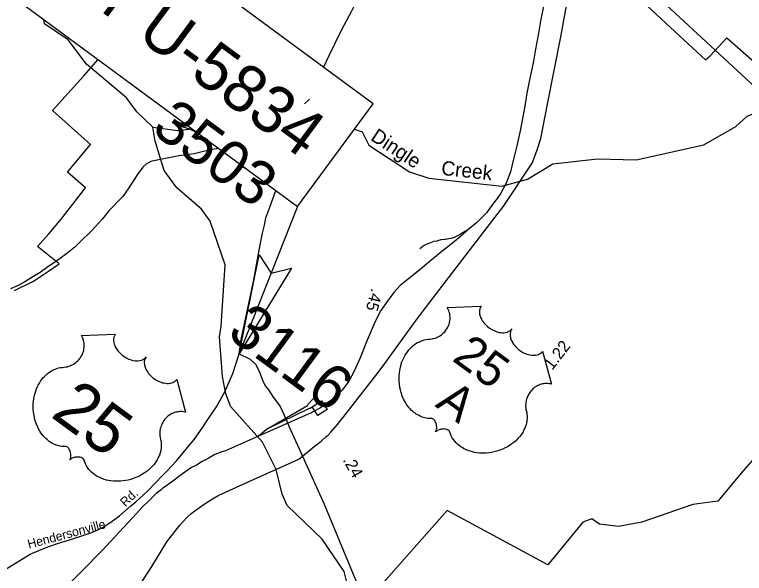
# Model space of a CAD drawing. Extents: x 945666 to 965748, y 644452 to 663300.
# Drawn here: x 953745 to 954740, y 659246 to 660009 of the extents above; entities that cross this region are included whole.
import ezdxf

# ---------------------------------------------------------------- set-up
doc = ezdxf.new("R2010")
doc.units = 0
for name, color, linetype in [('Default', 7, 'Continuous'), ('Exist Boundary Political City Limit New', 7, 'Continuous'), ('Exist Hydrographic Creek Single Shore', 7, 'Continuous'), ('Exist Hydrographic Misc Water Feature', 7, 'Continuous'), ('Exist Railroad Mainline', 7, 'Continuous'), ('Exist Railroad Station CELL', 7, 'Continuous'), ('Exist Road Primary US Label', 7, 'Continuous'), ('Exist Road Primary US Mileage Hundredths English Label', 7, 'Continuous'), ('Exist Road Primary US Shield Number Label', 7, 'Continuous'), ('Exist Road Primary US UnDivided 4 Lane Attributed', 7, 'Continuous'), ('Exist Road Secondary Mileage Tenths English Label', 7, 'Continuous'), ('Exist Road Secondary Type 51 Attributed', 7, 'Continuous'), ('Old_Level_1', 7, 'Continuous'), ('Old_Level_28', 7, 'Continuous'), ('Old_Level_48', 7, 'Continuous'), ('Prop EOT', 7, 'Continuous'), ('Prop Paved Shoulder', 7, 'Continuous'), ('Prop Terminator CELL', 7, 'Continuous')]:
    doc.layers.add(name, color=color, linetype=linetype)

msp = doc.modelspace()

# ---------------------------------------------------------------- linework, layer by layer
at = {"layer": 'Default'}
for points in [[(954051.13, 659546.04), (954065.89, 659538.88), (954073.22, 659532.08), (954078.17, 659522.36), (954082.73, 659509.91), (954086.54, 659502.22), (954090.86, 659496.7), (954097.47, 659486.7), (954102.05, 659481.22), (954107.02, 659474.06), (954115.33, 659456.27)], [(954115.33, 659456.27), (954119.23, 659446.4), (954137.42, 659406.62)], [(954137.42, 659406.62), (954167.04, 659340.74), (954214.25, 659226.89), (954219.17, 659214.5), (954234.76, 659177.83), (954248.16, 659148.39), (954278.06, 659087), (954292.16, 659061.01), (954331.21, 658991.49), (954355.24, 658946.97), (954361.3, 658935.37), (954368.18, 658920.76), (954371.98, 658911.32)]]:
    msp.add_lwpolyline(points, dxfattribs=at)
at = {"layer": 'Exist Boundary Political City Limit New'}
for points in [[(954575.32, 660503.3), (954575.7, 660500.3), (954583.86, 660480.88), (954594.94, 660465.46), (954605.03, 660449.51), (954618.55, 660420.1), (954630.56, 660394.58), (954633.25, 660364.3), (954630.95, 660333.19), (954616.56, 660298.85), (954554.44, 660217.43), (954494.31, 660125.89), (954651.37, 659980)], [(954651.37, 659980), (954686.77, 659947.19), (954692.96, 659952.82), (954715.96, 659977.25), (954922.31, 659795.6)], [(953744.79, 659632.28), (953770.6, 659644.99), (953791.02, 659658.63), (953805.5, 659668.87), (953776.31, 659692.7), (953791.81, 659709.74), (953808.51, 659729.83), (953841.4, 659772.67), (953817.2, 659793.89), (953848.59, 659831.85), (953796.78, 659878.21), (953839.23, 659925.52), (953858.88, 659947.47)], [(954764.84, 659416.94), (954738.12, 659386.29), (954703.48, 659345.2), (954669.25, 659340.27), (954599.91, 659316.21), (954568.17, 659310.66), (954542.24, 659313.52), (954531.6, 659320.72), (954519.65, 659316.53), (954471.84, 659258.02), (954334.37, 659332.51), (954199.61, 659179.31), (954181.17, 659196.36), (954156.43, 659171.36), (954118.74, 659203), (954109.85, 659196.66), (954100.54, 659204.87), (954083.83, 659205.72), (953921.01, 659022.58), (953828.63, 659098.16), (953806.55, 659063.26), (953767.75, 659001.98), (953738.57, 658955.88)]]:
    msp.add_lwpolyline(points, dxfattribs=at)
at = {"layer": 'Exist Hydrographic Creek Single Shore'}
for points in [[(953933.56, 659855.16), (953911.36, 659876), (953897.59, 659895.18), (953842.79, 659941.09), (953818.19, 659974.51), (953785.69, 659996.28), (953784.71, 660002.17)], [(954208.11, 659852.7), (954218.79, 659848.76), (954227.82, 659830.52), (954283.37, 659794.26), (954309.81, 659785.77), (954409.1, 659775.01), (954444.04, 659784.17), (954478.8, 659805.3), (954539.64, 659812.28), (954592.2, 659810.59), (954684.49, 659831.02), (954727.97, 659856.19), (954743.28, 659870.22), (954779.41, 659884.38), (954824.39, 659921.85), (954835.26, 659928.55), (954851.86, 659930.3), (954933.17, 659961.32), (954972.81, 659985.14)], [(954026.31, 659583.85), (954032.05, 659667.6), (954011.45, 659726.99), (953999.72, 659743.54), (953966.11, 659772.61), (953948.83, 659796.12), (953936.49, 659836.25), (953933.56, 659855.16)], [(953933.56, 659855.16), (953967.32, 659850.7), (953987.02, 659852.97)], [(954285.98, 659018.04), (954256.55, 659113.26), (954202.7, 659214.34), (954194.18, 659248.85), (954164.42, 659293.23), (954116.6, 659339.14), (954109.6, 659354.74), (954101.67, 659388.26), (954082.77, 659425.37), (954039.54, 659473.66), (954033.02, 659491.57), (954028.3, 659515.14), (954024.39, 659569.26), (954026.31, 659583.85)]]:
    msp.add_lwpolyline(points, dxfattribs=at)
at = {"layer": 'Exist Hydrographic Misc Water Feature'}
for p, q in [((954140.27, 659887.27), (954146.78, 659893.38)), ((954056.52, 659759.69), (954058.09, 659762.09))]:
    msp.add_line(p, q, dxfattribs=at)
for points in [[(953963.91, 659859.08), (953983.16, 659852.81), (953994.99, 659847.09)], [(954050.29, 659806.3), (954054.47, 659801.8), (954060.15, 659798.94), (954060.27, 659798.94)]]:
    msp.add_lwpolyline(points, dxfattribs=at)
at = {"layer": 'Exist Railroad Mainline'}
msp.add_line((954090.14, 659444.22), (954077.64, 659433.83), dxfattribs=at)
for points in [[(954467.99, 660031.57), (954462.18, 660002.69), (954459.26, 659983.44), (954454.84, 659961.67), (954452.12, 659945.27), (954446.3, 659917.49), (954443.27, 659901.53), (954440.44, 659884.14), (954437.5, 659869.62), (954433.96, 659850.19), (954429.73, 659829.79), (954424.48, 659809.75), (954420.71, 659794.15), (954414.8, 659778.91), (954407.54, 659765.13), (954402.68, 659758.12), (954397.35, 659751.04), (954388.13, 659738.55), (954374.42, 659724.58), (954362.54, 659715.21)], [(954362.54, 659715.21), (954354.82, 659707.82), (954341.9, 659697.11), (954325.24, 659683.68), (954312.12, 659673.34), (954294.93, 659658.81), (954281.92, 659648.39), (954270.62, 659639.22), (954261.91, 659629.79), (954252.6, 659617.6), (954243.99, 659605.29), (954236.24, 659589.96), (954225.6, 659564.59), (954216.17, 659540.44), (954207.53, 659521.71), (954200.59, 659508.77), (954191.57, 659496.56), (954177.37, 659483.39), (954168.9, 659477.21), (954165.58, 659474.98), (954161.86, 659472.52), (954153.1, 659467.85), (954148.71, 659465.21), (954148.19, 659464.96), (954077.64, 659433.83)], [(954362.54, 659715.21), (954359.79, 659713.24), (954352.14, 659708.81), (954347.85, 659706.73), (954343.97, 659704.76), (954339.49, 659703.26), (954336.72, 659702.81), (954332.24, 659702.17), (954331.12, 659701.96), (954326.71, 659701.47), (954325.99, 659701.38), (954321.21, 659700.33), (954320.28, 659699.96), (954316.28, 659699.17), (954309.37, 659696.74), (954305.9, 659695.11), (954303.33, 659693.65), (954297.14, 659689.16)], [(954090.14, 659444.22), (954144.03, 659475.69), (954145.34, 659477.26), (954150.22, 659482.98), (954155.17, 659487.63)], [(954090.14, 659444.22), (954146.95, 659471.73), (954147.84, 659472.12), (954151.72, 659474.51), (954155.09, 659476.65), (954158.01, 659479.13), (954160.06, 659481.51)], [(954077.64, 659433.83), (954032.56, 659413.87), (954027.66, 659412.26), (954018.07, 659408.66), (954008.94, 659403.21), (954000.46, 659398.98), (953992.93, 659394.01), (953986.11, 659390.87), (953973.97, 659382.36), (953958.83, 659370.77), (953946.62, 659362.1), (953944.59, 659360.43), (953938.6, 659355.79), (953928.94, 659346.44), (953918.18, 659336.22), (953911.09, 659328.12), (953905.21, 659321.67), (953870.08, 659284.17), (953864.21, 659277.93), (953855.1, 659268.59), (953846.88, 659259.86), (953836.11, 659249.21), (953832.76, 659245.77), (953650.24, 659062.44)]]:
    msp.add_lwpolyline(points, dxfattribs=at)
at = {"layer": 'Exist Railroad Station CELL'}
msp.add_lwpolyline([(954150.7, 659473.81), (954163.51, 659481.89), (954170.88, 659470.19), (954158.07, 659462.11)], close=True, dxfattribs=at)
at = {"layer": 'Exist Road Primary US UnDivided 4 Lane Attributed'}
for points in [[(954166.15, 659936.93), (954173.67, 659953.1), (954191.19, 659988.51), (954203.96, 660013.16), (954216.08, 660037.19), (954238.63, 660083.24), (954250.32, 660104.79), (954275.33, 660155.8), (954297.13, 660200.77), (954318.86, 660245.17), (954341.95, 660289.24), (954345.28, 660295.92), (954361.28, 660325.76), (954378.42, 660354.96), (954388.59, 660372.01), (954399.02, 660390.77), (954411.46, 660414.96), (954416.59, 660426.81), (954422.43, 660438.53), (954423.93, 660442.39)], [(954137.42, 659406.62), (954153.43, 659419.44), (954162.73, 659427.06), (954169.5, 659433.08), (954171.92, 659434.71), (954176.2, 659439.21), (954181.86, 659445.78), (954184.91, 659449.54), (954189.71, 659455.46), (954193.54, 659460.58), (954237.18, 659516.36), (954247.47, 659529.67), (954289.94, 659588.86), (954303.7, 659607.2), (954346.83, 659663.43), (954411.69, 659747.87), (954450.6, 659806.4), (954456.95, 659823.05), (954462.05, 659839.94), (954471.18, 659886.69), (954489.3, 659978.73), (954499.89, 660036.2)], [(954051.13, 659546.04), (954053.84, 659565.73), (954070.56, 659644.84), (954079.89, 659694.87), (954082.76, 659710.85), (954085.47, 659721.4), (954087.43, 659731.55), (954092.99, 659746.35), (954101, 659768.91)], [(953729.79, 659250.65), (953766.36, 659272.53), (953786.59, 659281.37), (953802.15, 659286.8), (953827.08, 659294.71), (953838.01, 659298.11), (953848.68, 659301.88), (953857.55, 659305.39), (953864.58, 659308.97), (953874.62, 659315.54), (953887.97, 659325.14), (953903.29, 659338.5), (953909.58, 659343.65), (953916.27, 659349.78), (953926.19, 659358.61), (953947.15, 659380.31), (953953, 659386.55), (953965.43, 659400.04), (953989.78, 659429.34), (954000.5, 659444.54), (954010.19, 659459.24), (954020.31, 659473.61), (954031.72, 659494.3), (954042.61, 659519.37), (954051.13, 659546.04)], [(953872.78, 659163.87), (953879.82, 659174.92), (953909.71, 659220.77), (953916.18, 659231.14), (953931.95, 659255.99), (953952.66, 659289.4), (953970.09, 659312.1), (953980.01, 659323.09), (953984.98, 659327.65), (953992.31, 659333.42), (954004.62, 659342.01), (954014.69, 659348.25), (954022.49, 659352.55), (954042.24, 659361.63), (954062.46, 659370.95), (954132.38, 659402.25), (954137.42, 659406.62)]]:
    msp.add_lwpolyline(points, dxfattribs=at)
at = {"layer": 'Exist Road Secondary Type 51 Attributed'}
msp.add_lwpolyline([(954023.53, 659826.04), (954013.81, 659825.01), (954011.56, 659824.33), (953989.64, 659819), (953968.77, 659816.16), (953932.69, 659809.07), (953930.85, 659808.29), (953924.37, 659804.73), (953919.95, 659800.68), (953911.87, 659790.07), (953900.51, 659772.55), (953892.31, 659760.78), (953873.36, 659741.25), (953864.65, 659730.3), (953849.92, 659713.94), (953834.03, 659698.2), (953827.22, 659691.63), (953817.87, 659684.26), (953808.7, 659677.64), (953799.26, 659670.88), (953790.32, 659664.81), (953779.88, 659657.17), (953770.02, 659651.06), (953759.14, 659644.29), (953749.71, 659639.48), (953739.41, 659634.94)], dxfattribs=at)
at = {"layer": 'Old_Level_28'}
msp.add_lwpolyline([(954708.22, 660405.29), (954708.61, 660402.28), (954716.76, 660382.87), (954727.84, 660367.45), (954737.94, 660351.5), (954751.45, 660322.09), (954763.46, 660296.56), (954766.15, 660266.28), (954763.85, 660235.17), (954749.46, 660200.83), (954687.34, 660119.41), (954627.21, 660027.87), (954784.27, 659881.98)], dxfattribs=at)
at = {"layer": 'Prop EOT'}
msp.add_line((954130.35, 659747.26), (954051.13, 659546.04), dxfattribs=at)
msp.add_lwpolyline([(954233.56, 659887.22), (953266.51, 660600.43), (953163.29, 660460.48), (954130.35, 659747.26)], close=True, dxfattribs=at)
at = {"layer": 'Prop Terminator CELL'}
for points in [[(954122.21, 659663.14), (954051.13, 659546.04), (954078.52, 659681.14), (954094.54, 659656.3)], [(954380.94, 659611.04), (954380.12, 659609.78), (954379.36, 659608.13), (954379.04, 659607.22), (954378.67, 659605.31), (954378.54, 659602.82), (954378.87, 659600.04), (954379.56, 659597.33), (954380.17, 659595.7), (954381.37, 659593.16), (954382.93, 659590.55), (954384.92, 659587.96), (954387.11, 659585.55), (954389.69, 659583.17), (954392.43, 659581.07), (954395.59, 659579.08), (954399.38, 659577.27), (954401.2, 659576.54), (954403.34, 659575.86), (954405.42, 659575.35), (954407.85, 659575), (954409.9, 659574.86), (954411.59, 659574.85), (954414.23, 659575.19), (954416.6, 659575.82), (954417.75, 659576.3), (954418.81, 659576.79), (954420.72, 659578.1), (954421.47, 659578.75), (954422.78, 659580.28), (954421.88, 659578.85), (954421.4, 659577.9), (954421.01, 659576.9), (954420.71, 659575.77), (954420.41, 659574.07), (954420.34, 659572.52), (954420.51, 659570.03), (954420.76, 659568.67), (954421.05, 659567.52), (954422.03, 659564.69), (954423.49, 659561.81), (954424.26, 659560.47), (954425.12, 659559.19), (954426.28, 659557.65), (954427.54, 659556.15), (954428.87, 659554.77), (954430.26, 659553.4), (954431.76, 659552.11), (954433.02, 659551.12), (954434.62, 659549.97), (954436.15, 659548.98), (954437.78, 659548.04), (954439.64, 659547.1), (954441.19, 659546.41), (954443.29, 659545.58), (954445.3, 659544.98), (954447.14, 659544.55), (954449.65, 659544.16), (954451.79, 659544), (954453.5, 659544.07), (954455.64, 659544.3), (954457.88, 659544.81), (954459.34, 659545.31), (954460.61, 659545.99), (954461.89, 659546.75), (954463.04, 659547.72), (954463.93, 659548.63), (954464.6, 659549.48), (954476.65, 659504.67), (954475.77, 659504.92), (954473.61, 659505.31), (954471.8, 659505.5), (954468.75, 659505.57), (954467.31, 659505.42), (954465.85, 659505.25), (954464.42, 659504.97), (954463.12, 659504.68), (954461.41, 659504.13), (954459.79, 659503.51), (954458.09, 659502.76), (954456.72, 659502.04), (954454.09, 659500.36), (954452.57, 659499.19), (954451.36, 659498.14), (954449.1, 659495.78), (954448.09, 659494.61), (954447.19, 659493.38), (954446.3, 659492.03), (954445.51, 659490.7), (954444.78, 659489.24), (954444.14, 659487.95), (954443.48, 659486.29), (954442.8, 659484.28), (954442.28, 659482.24), (954441.74, 659478.72), (954441.55, 659474.86), (954441.71, 659472.51), (954442, 659470.38), (954442.68, 659467.53), (954443.02, 659465.95), (954443.31, 659464), (954443.57, 659460.53), (954443.58, 659458.98), (954443.5, 659457.3), (954443.34, 659455.64), (954443.11, 659453.89), (954442.86, 659452.39), (954442.04, 659449.13), (954441, 659446.15), (954440.4, 659444.62), (954438.83, 659441.35), (954437.99, 659439.78), (954436.16, 659436.82), (954433.67, 659433.43), (954431.04, 659430.41), (954427.68, 659427.11), (954425.52, 659425.24), (954422.83, 659423.2), (954420.42, 659421.48), (954416.63, 659419.14), (954413.67, 659417.59), (954410.05, 659415.9), (954407.73, 659414.96), (954405.16, 659414.04), (954402.07, 659413.06), (954398.62, 659412.14), (954394.72, 659411.37), (954391.69, 659410.91), (954387.91, 659410.55), (954385.7, 659410.43), (954382.63, 659410.4), (954378.62, 659410.59), (954374.83, 659411.01), (954371.72, 659411.52), (954369.08, 659412.13), (954365.77, 659413.06), (954360.58, 659415.05), (954358.77, 659415.88), (954356.7, 659416.98), (954354.83, 659418.09), (954353.06, 659419.23), (954350.79, 659420.91), (954348.65, 659422.75), (954346.74, 659424.64), (954344.86, 659426.74), (954343.04, 659429.15), (954341.54, 659431.54), (954340.18, 659434.17), (954338.24, 659439.11), (954337.61, 659440.43), (954337.14, 659441.02), (954335.79, 659442.12), (954334.27, 659442.81), (954332.53, 659443.27), (954331.41, 659443.44), (954329.81, 659443.52), (954328.49, 659443.48), (954326.79, 659443.27), (954325.52, 659442.98), (954324.53, 659442.75), (954322.33, 659441.9), (954321.41, 659441.4), (954320.3, 659440.7), (954318.9, 659439.5), (954319.79, 659441.66), (954320.15, 659443.27), (954320.29, 659444.76), (954320.32, 659446.15), (954320.17, 659448.08), (954319.9, 659449.63), (954319.46, 659451.34), (954318.81, 659452.91), (954318.22, 659454.09), (954317.6, 659455.05), (954316.74, 659456.09), (954315.93, 659456.8), (954315.21, 659457.3), (954314.07, 659457.8), (954312.05, 659457.82), (954310.16, 659457.88), (954308.18, 659458.04), (954305.92, 659458.37), (954304.32, 659458.69), (954302.5, 659459.19), (954300.44, 659459.86), (954298.3, 659460.71), (954296.19, 659461.71), (954294.37, 659462.65), (954292.52, 659463.78), (954290.91, 659464.88), (954289.28, 659466.11), (954287.84, 659467.36), (954286.18, 659468.83), (954284.21, 659470.78), (954282.69, 659472.55), (954281.14, 659474.49), (954279.61, 659476.57), (954278.09, 659478.95), (954276.28, 659482.07), (954275.14, 659484.38), (954273.46, 659488.2), (954271.79, 659493.08), (954270.75, 659497.07), (954270.12, 659500.17), (954269.43, 659505.05), (954269.16, 659508.1), (954269.04, 659513.3), (954269.17, 659516.91), (954269.41, 659519.45), (954269.95, 659523.43), (954270.4, 659525.84), (954271.21, 659529.24), (954272.08, 659532.25), (954273.01, 659535.03), (954273.68, 659536.74), (954274.97, 659539.65), (954275.95, 659541.68), (954277.41, 659544.35), (954279.13, 659547.06), (954280.84, 659549.45), (954282.35, 659551.37), (954284.27, 659553.5), (954286.45, 659555.65), (954288.46, 659557.39), (954289.99, 659558.58), (954291.96, 659559.96), (954294.27, 659561.37), (954296.66, 659562.59), (954298.76, 659563.52), (954301.19, 659564.39), (954303.41, 659565.02), (954306.1, 659565.54), (954308.75, 659565.88), (954311.03, 659565.98), (954313.94, 659566.39), (954315.56, 659566.75), (954317.65, 659567.36), (954319.45, 659568.03), (954320.97, 659568.69), (954323.12, 659569.75), (954324.6, 659570.63), (954326.72, 659572.1), (954328.08, 659573.23), (954329.73, 659574.76), (954331.19, 659576.26), (954332.82, 659578.29), (954334.04, 659580.05), (954335.3, 659582.24), (954336.35, 659584.45), (954337.14, 659586.48), (954337.84, 659588.95), (954338.22, 659590.85), (954338.51, 659593.59), (954338.58, 659596.29), (954338.37, 659598.69), (954338.03, 659600.93), (954337.5, 659602.82), (954336.94, 659604.53), (954336.12, 659606.53), (954335.21, 659608.29), (954334.57, 659609.31)], [(953882.27, 659572.75), (953881.45, 659571.48), (953880.69, 659569.83), (953880.36, 659568.93), (953879.99, 659567.02), (953879.86, 659564.53), (953880.2, 659561.75), (953880.88, 659559.03), (953881.5, 659557.41), (953882.7, 659554.87), (953884.26, 659552.25), (953886.24, 659549.67), (953888.43, 659547.26), (953891.01, 659544.87), (953893.75, 659542.77), (953896.92, 659540.78), (953900.7, 659538.98), (953902.53, 659538.24), (953904.67, 659537.57), (953906.74, 659537.06), (953909.17, 659536.7), (953911.23, 659536.57), (953912.91, 659536.56), (953915.56, 659536.9), (953917.92, 659537.52), (953919.08, 659538), (953920.14, 659538.5), (953922.05, 659539.81), (953922.79, 659540.46), (953924.11, 659541.98), (953923.21, 659540.55), (953922.72, 659539.61), (953922.34, 659538.61), (953922.03, 659537.48), (953921.74, 659535.78), (953921.66, 659534.23), (953921.83, 659531.74), (953922.08, 659530.38), (953922.38, 659529.23), (953923.36, 659526.4), (953924.81, 659523.52), (953925.58, 659522.18), (953926.45, 659520.9), (953927.6, 659519.35), (953928.87, 659517.86), (953930.2, 659516.48), (953931.58, 659515.11), (953933.08, 659513.82), (953934.35, 659512.83), (953935.95, 659511.68), (953937.48, 659510.68), (953939.11, 659509.75), (953940.97, 659508.8), (953942.51, 659508.12), (953944.61, 659507.29), (953946.62, 659506.68), (953948.46, 659506.26), (953950.98, 659505.87), (953953.12, 659505.7), (953954.82, 659505.78), (953956.96, 659506.01), (953959.2, 659506.52), (953960.66, 659507.01), (953961.94, 659507.7), (953963.22, 659508.46), (953964.37, 659509.42), (953965.26, 659510.34), (953965.93, 659511.19), (953977.97, 659466.38), (953977.09, 659466.63), (953974.93, 659467.02), (953973.13, 659467.21), (953970.07, 659467.27), (953968.64, 659467.13), (953967.18, 659466.96), (953965.75, 659466.68), (953964.45, 659466.38), (953962.74, 659465.83), (953961.11, 659465.22), (953959.42, 659464.47), (953958.05, 659463.75), (953955.42, 659462.06), (953953.89, 659460.9), (953952.69, 659459.84), (953950.42, 659457.49), (953949.42, 659456.31), (953948.51, 659455.09), (953947.63, 659453.74), (953946.83, 659452.41), (953946.1, 659450.95), (953945.47, 659449.66), (953944.8, 659447.99), (953944.12, 659445.99), (953943.6, 659443.95), (953943.07, 659440.43), (953942.88, 659436.57), (953943.03, 659434.22), (953943.32, 659432.08), (953944, 659429.24), (953944.34, 659427.65), (953944.64, 659425.71), (953944.9, 659422.23), (953944.9, 659420.69), (953944.83, 659419.01), (953944.66, 659417.35), (953944.44, 659415.59), (953944.19, 659414.1), (953943.37, 659410.84), (953942.32, 659407.85), (953941.73, 659406.32), (953940.16, 659403.06), (953939.32, 659401.49), (953937.48, 659398.53), (953935, 659395.14), (953932.37, 659392.12), (953929, 659388.82), (953926.85, 659386.94), (953924.16, 659384.9), (953921.75, 659383.19), (953917.96, 659380.85), (953914.99, 659379.3), (953911.37, 659377.6), (953909.06, 659376.67), (953906.48, 659375.74), (953903.4, 659374.77), (953899.95, 659373.85), (953896.05, 659373.08), (953893.02, 659372.62), (953889.24, 659372.26), (953887.02, 659372.14), (953883.96, 659372.1), (953879.94, 659372.29), (953876.16, 659372.72), (953873.04, 659373.23), (953870.41, 659373.84), (953867.09, 659374.77), (953861.9, 659376.75), (953860.09, 659377.58), (953858.02, 659378.68), (953856.16, 659379.79), (953854.39, 659380.94), (953852.11, 659382.62), (953849.98, 659384.46), (953848.07, 659386.34), (953846.19, 659388.45), (953844.37, 659390.86), (953842.87, 659393.25), (953841.5, 659395.88), (953839.57, 659400.82), (953838.93, 659402.14), (953838.46, 659402.73), (953837.11, 659403.83), (953835.6, 659404.52), (953833.86, 659404.98), (953832.73, 659405.14), (953831.13, 659405.23), (953829.82, 659405.19), (953828.12, 659404.97), (953826.84, 659404.69), (953825.86, 659404.46), (953823.66, 659403.6), (953822.74, 659403.11), (953821.63, 659402.41), (953820.23, 659401.2), (953821.12, 659403.37), (953821.47, 659404.97), (953821.62, 659406.47), (953821.64, 659407.86), (953821.49, 659409.78), (953821.23, 659411.34), (953820.78, 659413.05), (953820.13, 659414.62), (953819.55, 659415.8), (953818.93, 659416.76), (953818.07, 659417.8), (953817.26, 659418.5), (953816.54, 659419.01), (953815.4, 659419.5), (953813.38, 659419.52), (953811.49, 659419.58), (953809.5, 659419.74), (953807.24, 659420.08), (953805.65, 659420.4), (953803.83, 659420.89), (953801.76, 659421.56), (953799.62, 659422.42), (953797.51, 659423.42), (953795.7, 659424.35), (953793.84, 659425.48), (953792.23, 659426.59), (953790.61, 659427.82), (953789.16, 659429.07), (953787.5, 659430.53), (953785.53, 659432.49), (953784.01, 659434.25), (953782.46, 659436.2), (953780.94, 659438.28), (953779.41, 659440.66), (953777.61, 659443.77), (953776.46, 659446.08), (953774.78, 659449.91), (953773.11, 659454.79), (953772.07, 659458.78), (953771.44, 659461.88), (953770.75, 659466.76), (953770.49, 659469.81), (953770.37, 659475.01), (953770.5, 659478.62), (953770.74, 659481.16), (953771.27, 659485.14), (953771.73, 659487.54), (953772.53, 659490.95), (953773.41, 659493.95), (953774.34, 659496.73), (953775, 659498.45), (953776.3, 659501.36), (953777.27, 659503.39), (953778.74, 659506.06), (953780.46, 659508.77), (953782.16, 659511.16), (953783.68, 659513.08), (953785.59, 659515.21), (953787.78, 659517.36), (953789.78, 659519.1), (953791.31, 659520.29), (953793.28, 659521.66), (953795.59, 659523.08), (953797.98, 659524.3), (953800.09, 659525.22), (953802.52, 659526.1), (953804.74, 659526.72), (953807.43, 659527.24), (953810.07, 659527.58), (953812.35, 659527.69), (953815.26, 659528.1), (953816.88, 659528.45), (953818.97, 659529.07), (953820.77, 659529.74), (953822.3, 659530.4), (953824.45, 659531.45), (953825.92, 659532.34), (953828.05, 659533.81), (953829.4, 659534.94), (953831.06, 659536.46), (953832.52, 659537.97), (953834.14, 659540), (953835.36, 659541.76), (953836.63, 659543.94), (953837.68, 659546.16), (953838.46, 659548.19), (953839.17, 659550.65), (953839.55, 659552.56), (953839.84, 659555.3), (953839.91, 659557.99), (953839.69, 659560.39), (953839.35, 659562.64), (953838.82, 659564.52), (953838.26, 659566.24), (953837.44, 659568.23), (953836.53, 659570), (953835.9, 659571.02)]]:
    msp.add_lwpolyline(points, close=True, dxfattribs=at)

# ---------------------------------------------------------------- texts
at = {"layer": 'Exist Road Primary US Label'}
for s, height, rotation, p in [('Rd.', 12.341, 43.66562, (953895.94, 659336.69)), ('Hendersonville', 12.3409, 15.03538, (953764.52, 659280.05))]:
    msp.add_text(s, height=height, rotation=rotation, dxfattribs=at).set_placement(p)
at = {"layer": 'Exist Road Primary US Mileage Hundredths English Label'}
for s, rotation, p in [('.45', 255.06326, (954231.44, 659636.01)), ('1.22', 52.51221, (954477.8, 659522.87))]:
    msp.add_text(s, height=16.238, rotation=rotation, dxfattribs=at).set_placement(p)
at = {"layer": 'Exist Road Primary US Shield Number Label'}
for s, height, p in [('25', 46.953, (954339.98, 659537.7)), ('25', 66.589, (953792.69, 659461.14)), ('A', 46.95, (954316.96, 659474.92))]:
    msp.add_text(s, height=height, rotation=323.59084, dxfattribs=at).set_placement(p)
at = {"layer": 'Exist Road Secondary Mileage Tenths English Label'}
msp.add_text('.24', height=16.238, rotation=299.11146, dxfattribs=at).set_placement((954191.85, 659401.28))
at = {"layer": 'Old_Level_1'}
for s, p in [('3503', (953929.63, 659849.32)), ('3116', (954032.56, 659570.7))]:
    msp.add_text(s, height=60, rotation=323.59084, dxfattribs=at).set_placement(p)
at = {"layer": 'Old_Level_48'}
msp.add_text('BEGIN TIP PROJECT U-5834', height=64.231, rotation=323.59084, dxfattribs=at).set_placement((953206.54, 660497.03))
at = {"layer": 'Prop Paved Shoulder'}
for s, rotation, p in [('Dingle', 326.79152, (954229.03, 659838.46)), ('Creek', 353.81813, (954325.89, 659790.29))]:
    msp.add_text(s, height=19.486, rotation=rotation, dxfattribs=at).set_placement(p)

doc.saveas('drawing.dxf')
